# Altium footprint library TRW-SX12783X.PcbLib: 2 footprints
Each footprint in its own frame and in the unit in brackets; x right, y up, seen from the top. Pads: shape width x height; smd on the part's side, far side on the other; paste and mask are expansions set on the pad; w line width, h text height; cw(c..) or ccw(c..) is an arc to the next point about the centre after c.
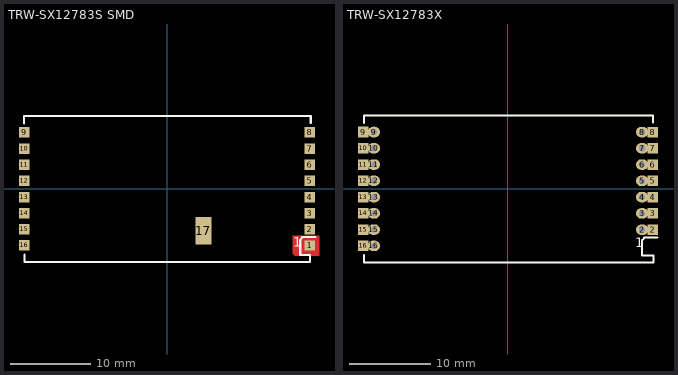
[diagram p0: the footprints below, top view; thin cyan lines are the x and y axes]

## TRW-SX12783S SMD [mm]
pads (17):
  rect 1.3x1.3 smd mask+0.102: 1(17.691,-7.002) 2(17.691,-5.002) 3(17.691,-3.002) 4(17.691,-1.002) 5(17.691,0.998) 6(17.691,2.998) 7(17.691,4.998) 8(17.691,6.998) 9(-17.691,7.002) 10(-17.691,5.002) 11(-17.691,3.002) 12(-17.691,1.002) 13(-17.691,-0.998) 14(-17.691,-2.998) 15(-17.691,-4.998) 16(-17.691,-6.998)
  rect 2x3.4 smd: 17(4.5,-5.2)
Top Layer:
  pour cut-out: 18.825,-5.8 15.575,-5.8 15.575,-8.05 15.825,-8.3 18.825,-8.3
  lines w0.305: -17.741,5.002 -17.741,5.002
Top Overlay:
  lines w0.254: -17.704,8.1 -17.704,9.014 17.8,9.014 17.8,8.176 ; -17.678,-8.105 -17.678,-9.02 17.704,-9.02 17.704,-8.182 16.5,-8.182 16.5,-7.379 16.5,-6.3 16.828,-5.972 ; 16.728,-5.972 18.4,-5.972
  text "1" at 15.621,-7.6 h2.03

## TRW-SX12783X [mm] "DIP"
pads (30):
  oval 1.5x1.3 / inner round 1 / far side oval 1.5x1.3 hole 0.762 mask+0.102: 2(16.491,-5.002) 3(16.491,-3.002) 4(16.491,-1.002) 5(16.491,0.998) 6(16.491,2.998) 7(16.491,4.998) 8(16.491,6.998) 9(-16.491,7.002) 10(-16.491,5.002) 11(-16.491,3.002) 12(-16.491,1.002) 13(-16.491,-0.998) 14(-16.491,-2.998) 15(-16.491,-4.998) 16(-16.491,-6.998)
  rect 1.3x1.3 smd mask+0.102: 2(17.791,-5.002) 3(17.791,-3.002) 4(17.791,-1.002) 5(17.791,0.998) 6(17.791,2.998) 7(17.791,4.998) 8(17.791,6.998) 9(-17.791,7.002) 10(-17.791,5.002) 11(-17.791,3.002) 12(-17.791,1.002) 13(-17.791,-0.998) 14(-17.791,-2.998) 15(-17.791,-4.998) 16(-17.791,-6.998)
Top Layer:
  lines w0.305: -16.851,-7.002 -16.849,-7.004
Top Overlay:
  lines w0.254: -17.704,8.1 -17.704,9.014 17.8,9.014 17.8,8.176 ; -17.678,-8.105 -17.678,-9.02 17.9,-9.02 17.9,-8.181 16.5,-8.181 16.5,-7.379 16.5,-6.3 16.828,-5.972 ; 16.728,-5.972 18.4,-5.972
  text "1" at 15.621,-7.6 h2.03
